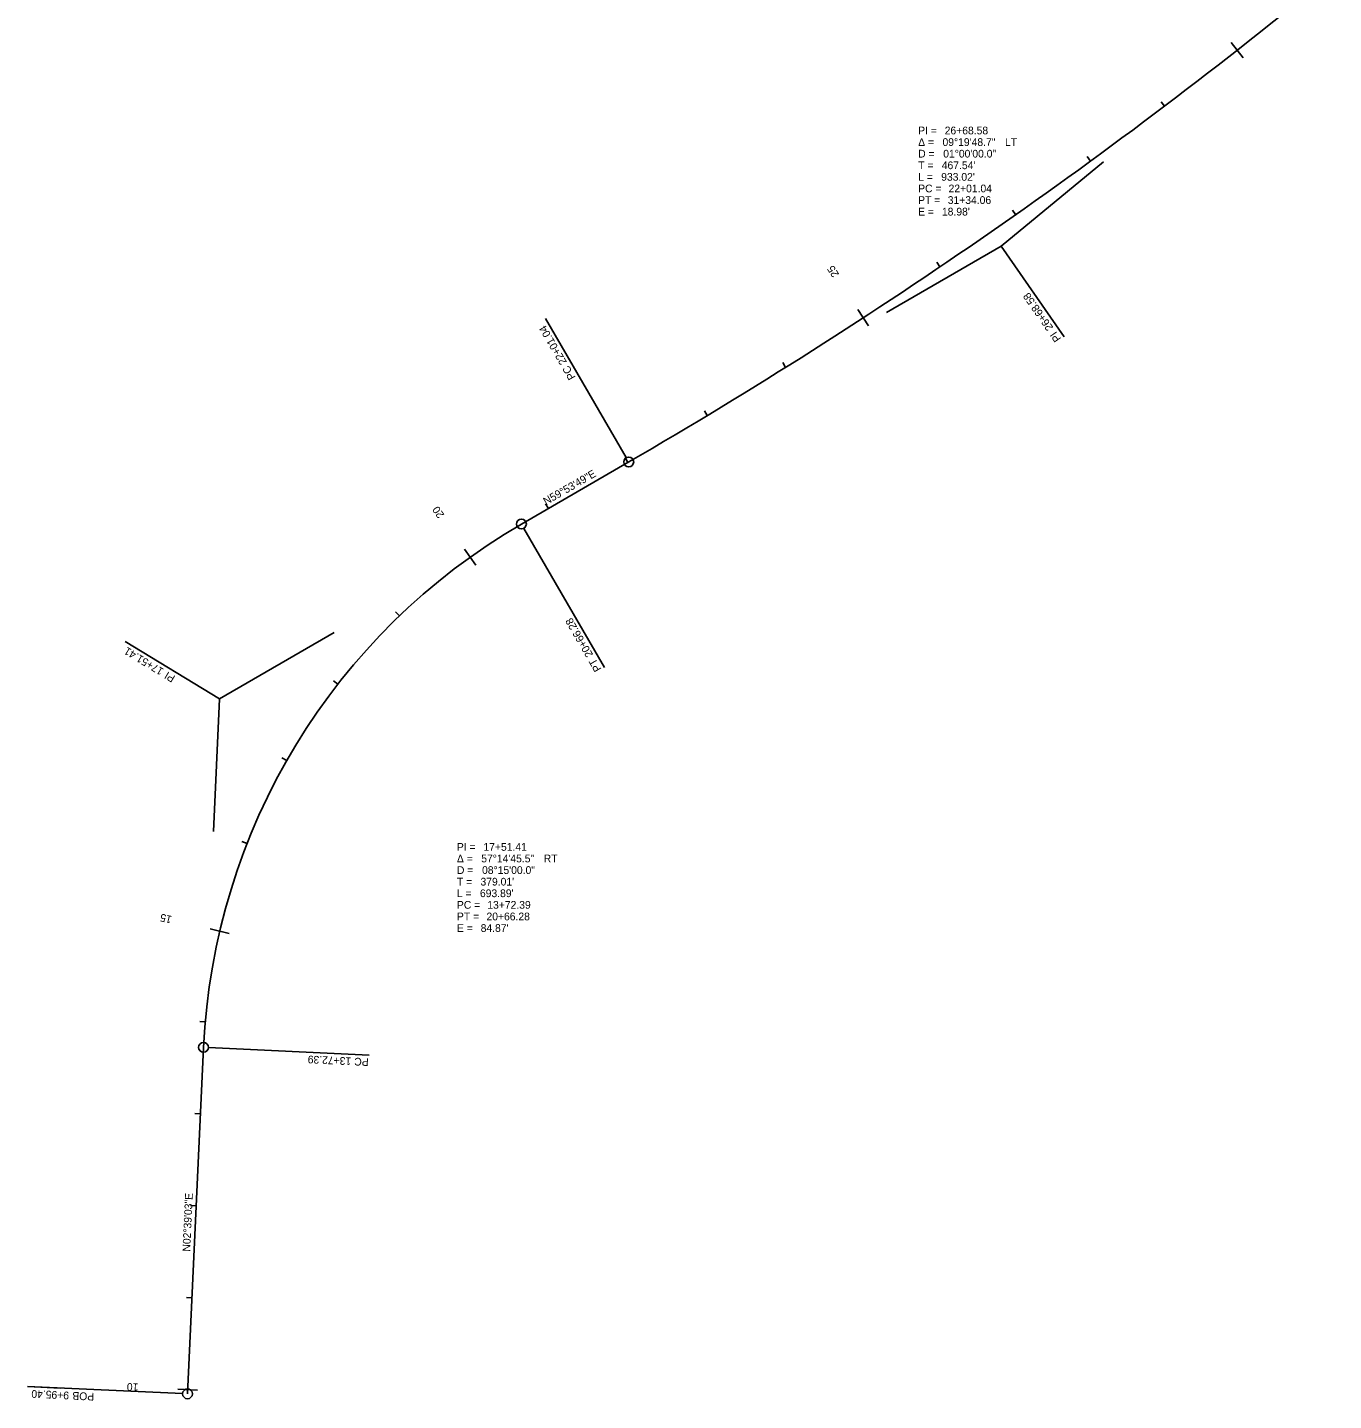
# Model space of a CAD drawing. Extents: x 1145421 to 1155673, y 2015317 to 2021442.
# Drawn here: x 1145421 to 1146840, y 2015317 to 2016809 of the extents above; entities that cross this region are included whole.
import ezdxf

# ---------------------------------------------------------------- set-up
doc = ezdxf.new("R2010")
doc.units = 0
for name, color, linetype in [('Default', 7, 'Continuous'), ('EX_CONTOUR_ANNOT_MINOR', 7, 'Continuous'), ('EX_TERRAIN', 7, 'Continuous')]:
    doc.layers.add(name, color=color, linetype=linetype)

msp = doc.modelspace()

# ---------------------------------------------------------------- linework, layer by layer
at = {"layer": 'Default'}
for p, q in [((1145957.8, 2016269.6), (1146074.4, 2016337.1)), ((1145595, 2015324.3), (1145612.4, 2015700.8))]:
    msp.add_line(p, q, dxfattribs=at)
for centre, radius, start, end in [((1143200.7, 2021293.9), 5729.6, 300.1031, 309.4333), ((1146306.2, 2015668.7), 694.5, 120.1031, 177.3491)]:
    msp.add_arc(centre, radius, start, end, dxfattribs=at)
at = {"layer": 'EX_CONTOUR_ANNOT_MINOR'}
for p, q in [((1146728.9, 2016793.1), (1146742, 2016776.4)), ((1146652.6, 2016728.5), (1146656.2, 2016723.7)), ((1146572.4, 2016668.9), (1146575.9, 2016664.1)), ((1146478.9, 2016571.6), (1146590.1, 2016663.1)), ((1146491.2, 2016610.8), (1146494.6, 2016605.9)), ((1146478.9, 2016571.6), (1146354.3, 2016499.4)), ((1146478.9, 2016571.6), (1146547.3, 2016473.1)), ((1146409, 2016554.1), (1146412.3, 2016549.1)), ((1146323.2, 2016502.7), (1146334.8, 2016484.9)), ((1146071.7, 2016341.8), (1145984.1, 2016492.9)), ((1145984.1, 2016492.9), (1145984.1, 2016492.9)), ((1146547.3, 2016473.1), (1146547.3, 2016473.1)), ((1146241.6, 2016445), (1146244.8, 2016439.9)), ((1146156.5, 2016392.6), (1146159.6, 2016387.5)), ((1146070.5, 2016341.8), (1146073.5, 2016336.6)), ((1146074.4, 2016337.1), (1146074.4, 2016337.1)), ((1145984, 2016291.7), (1145987, 2016286.5)), ((1145957.8, 2016269.6), (1145957.8, 2016269.6)), ((1145960.5, 2016264.9), (1146048.1, 2016113.8)), ((1145895.9, 2016242.3), (1145908.3, 2016225)), ((1145821.1, 2016174.1), (1145825.3, 2016169.8)), ((1145629.9, 2016079.5), (1145754.5, 2016151.7)), ((1145629.9, 2016079.5), (1145527.4, 2016141.8)), ((1145527.4, 2016141.8), (1145527.4, 2016141.8)), ((1146048.1, 2016113.8), (1146048.1, 2016113.8)), ((1145753.6, 2016099.3), (1145758.4, 2016095.6)), ((1145629.9, 2016079.5), (1145623.3, 2015935.6)), ((1145697.6, 2016015.6), (1145702.8, 2016012.6)), ((1145654.1, 2015924.6), (1145659.7, 2015922.5)), ((1145619.6, 2015829.5), (1145640.2, 2015824.7)), ((1145608.3, 2015728.9), (1145614.2, 2015728.4)), ((1145612.4, 2015700.8), (1145612.4, 2015700.8)), ((1145617.7, 2015700.6), (1145792.2, 2015692.5)), ((1145792.2, 2015692.5), (1145792.2, 2015692.5)), ((1145603.1, 2015628.8), (1145609.1, 2015628.5)), ((1145598.4, 2015528.9), (1145604.4, 2015528.6)), ((1145593.8, 2015429), (1145599.8, 2015428.7)), ((1145589.6, 2015324.5), (1145421.2, 2015332.3)), ((1145421.2, 2015332.3), (1145457.1, 2015330.6)), ((1145584.5, 2015329.3), (1145605.7, 2015328.4)), ((1145595, 2015324.3), (1145595, 2015324.3))]:
    msp.add_line(p, q, dxfattribs=at)
for centre in [(1146074.4, 2016337.1), (1145957.8, 2016269.6), (1145612.4, 2015700.8), (1145595, 2015324.3)]:
    msp.add_circle(centre, 5.34, dxfattribs=at)
at = {"layer": 'EX_TERRAIN'}
for p, q in [((1145957.8, 2016269.6), (1146074.4, 2016337.1)), ((1145595, 2015324.3), (1145612.4, 2015700.8))]:
    msp.add_line(p, q, dxfattribs=at)
for centre, radius, start, end in [((1143200.7, 2021293.9), 5729.6, 300.1031, 309.4333), ((1146306.2, 2015668.7), 694.5, 120.1031, 177.3491)]:
    msp.add_arc(centre, radius, start, end, dxfattribs=at)

# ---------------------------------------------------------------- texts
at = {"layer": 'EX_CONTOUR_ANNOT_MINOR'}
for s, p in [('PI = ', (1146388.8, 2016693.1)), ('26+68.58', (1146417.6, 2016693.1)), ('Δ = ', (1146388.8, 2016680.5)), ('09°19\'48.7"', (1146415.2, 2016680.5)), (' LT', (1146480, 2016680.5)), ('D = ', (1146388.8, 2016667.9)), ('01°00\'00.0"', (1146416, 2016667.9)), ('T = ', (1146388.8, 2016655.3)), ('L = ', (1146388.8, 2016642.7)), ("933.02'", (1146413.8, 2016642.7)), ("467.54'", (1146414.4, 2016655.3)), ('PC = ', (1146388.8, 2016630.1)), ('22+01.04', (1146421.8, 2016630.1)), ('PT = ', (1146388.8, 2016617.5)), ('31+34.06', (1146420.9, 2016617.5)), ('E = ', (1146388.8, 2016604.9)), ("18.98'", (1146414.6, 2016604.9)), ('PI = ', (1145887.7, 2015914.5)), ('17+51.41', (1145916.5, 2015914.5)), ('Δ = ', (1145887.7, 2015901.9)), ('57°14\'45.5"', (1145914.1, 2015901.9)), (' RT', (1145978.9, 2015901.9)), ('D = ', (1145887.7, 2015889.3)), ('08°15\'00.0"', (1145915, 2015889.3)), ('T = ', (1145887.7, 2015876.7)), ("379.01'", (1145913.3, 2015876.7)), ('L = ', (1145887.7, 2015864.1)), ('PC = ', (1145887.7, 2015851.5)), ("693.89'", (1145912.7, 2015864.1)), ('13+72.39', (1145920.7, 2015851.5)), ('PT = ', (1145887.7, 2015838.9)), ('20+66.28', (1145919.8, 2015838.9)), ('E = ', (1145887.7, 2015826.3)), ("84.87'", (1145913.5, 2015826.3))]:
    msp.add_text(s, height=8.4, dxfattribs=at).set_placement(p)
for s, rotation, p in [('25', 123.0927, (1146303.2, 2016541.1)), ('26+68.58', 124.7682, (1146535.9, 2016483.2)), ('22+01.04', 120.1031, (1146007.4, 2016445.6)), ('PI ', 124.7682, (1146544.4, 2016471)), ('PC', 120.1031, (1146016.9, 2016429.2)), ('N59°53\'49"E', 30.1031, (1145984.5, 2016289.9)), ('20', 125.5716, (1145874.4, 2016279.7)), ('20+66.28', 120.1031, (1146035.9, 2016127.7)), ('17+51.41', 148.7261, (1145569.8, 2016111.8)), ('PT', 120.1031, (1146045, 2016112)), ('PI ', 148.7261, (1145582.4, 2016104.1)), ('15', 166.8216, (1145578.6, 2015843.4)), ('13+72.39', 177.3491, (1145773, 2015689.8)), ('PC', 177.3491, (1145792, 2015688.9)), ('N02°39\'03"E', 87.3491, (1145597.9, 2015478.7)), ('9+95.40', 177.3491, (1145466.5, 2015326.6)), ('POB ', 177.3491, (1145493.8, 2015325.3)), ('10', 177.3491, (1145541.8, 2015335.5))]:
    msp.add_text(s, height=8.4, rotation=rotation, dxfattribs=at).set_placement(p)

doc.saveas('drawing.dxf')
